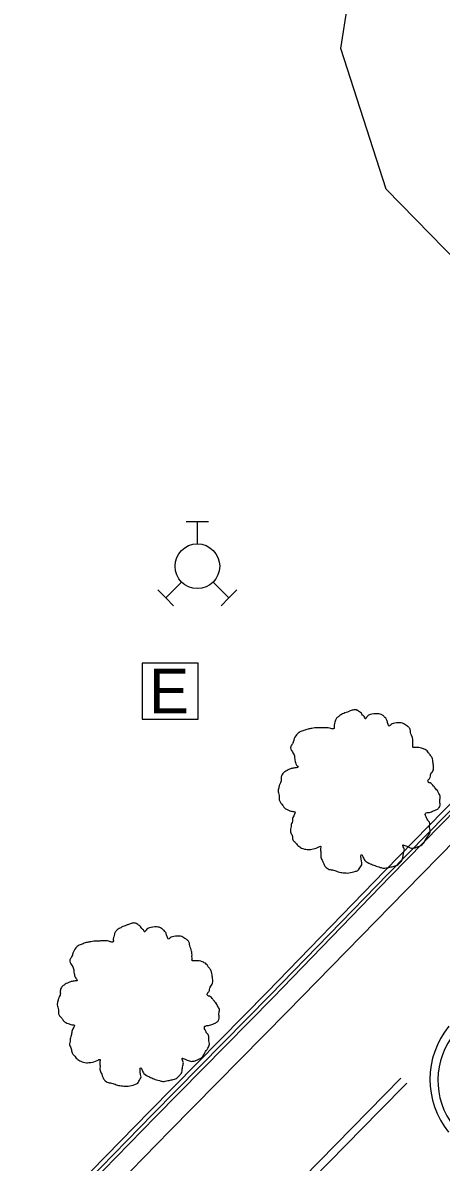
# Model space of a CAD drawing. Extents: x 2004847 to 2009016, y 1134161 to 1140101.
# Drawn here: x 2008292.1 to 2008329.5, y 1139615.9 to 1139717.9 of the extents above; entities that cross this region are included whole.
import ezdxf

# ---------------------------------------------------------------- set-up
doc = ezdxf.new("R2010")
doc.units = 0
for name, color, linetype in [('RD_EX_Curb', 7, 'Continuous'), ('RD_EX_Pavement_Markings', 7, 'Continuous'), ('RD_EX_Road', 7, 'Continuous'), ('RD_EX_SU_Elec', 7, 'Continuous'), ('RD_EX_UT', 7, 'Continuous'), ('RD_EX_VEG', 7, 'Continuous')]:
    doc.layers.add(name, color=color, linetype=linetype)

msp = doc.modelspace()

# ---------------------------------------------------------------- linework, layer by layer
at = {"layer": 'RD_EX_Curb'}
for points in [[(2008313.95, 1139631.15), (2008324.47, 1139642), (2008334.92, 1139652.7), (2008345.38, 1139663.43), (2008355.73, 1139674.16), (2008362.76, 1139681.32), (2008369.08, 1139687.77), (2008373.9, 1139692.85), (2008375.94, 1139695.31)], [(2008314.23, 1139630.88), (2008324.76, 1139641.72), (2008335.24, 1139652.39), (2008345.69, 1139663.14), (2008356.1, 1139673.82), (2008363.13, 1139680.99), (2008369.36, 1139687.52), (2008374.19, 1139692.61), (2008376.26, 1139695.09)], [(2008314.47, 1139630.64), (2008324.97, 1139641.51), (2008335.45, 1139652.2), (2008345.91, 1139662.92), (2008356.3, 1139673.64), (2008363.33, 1139680.8), (2008369.58, 1139687.31), (2008374.38, 1139692.45), (2008376.45, 1139694.96)], [(2008147.05, 1139457.63), (2008157.17, 1139468.78), (2008167.34, 1139479.93), (2008177.6, 1139490.95), (2008187.99, 1139502), (2008198.38, 1139512.83), (2008208.83, 1139523.6), (2008219.3, 1139534.36), (2008229.8, 1139545.07), (2008234.36, 1139549.78), (2008240.49, 1139556.23), (2008251, 1139566.93), (2008261.51, 1139577.61), (2008272.02, 1139588.33), (2008282.51, 1139599.04), (2008292.98, 1139609.77), (2008303.46, 1139620.49), (2008313.95, 1139631.15)], [(2008147.33, 1139457.38), (2008157.45, 1139468.53), (2008167.61, 1139479.68), (2008177.88, 1139490.7), (2008188.26, 1139501.74), (2008198.64, 1139512.57), (2008209.09, 1139523.35), (2008219.56, 1139534.1), (2008230.06, 1139544.81), (2008234.71, 1139549.44), (2008240.85, 1139555.89), (2008251.29, 1139566.64), (2008261.8, 1139577.33), (2008272.3, 1139588.06), (2008282.78, 1139598.77), (2008293.28, 1139609.48), (2008303.73, 1139620.23), (2008314.23, 1139630.88)], [(2008241.04, 1139555.7), (2008242.78, 1139557.49), (2008251.51, 1139566.43), (2008262.02, 1139577.12), (2008272.55, 1139587.82), (2008283.03, 1139598.53), (2008293.51, 1139609.26), (2008303.97, 1139619.99), (2008314.47, 1139630.64)]]:
    msp.add_lwpolyline(points, dxfattribs=at)
msp.add_ellipse((2008335.93, 1139623.25), major_axis=(-6.6, 1.24), ratio=0.998768, start_param=5.777021, end_param=7.134281, dxfattribs=at)
at = {"layer": 'RD_EX_Pavement_Markings'}
for points in [[(2008152.69, 1139442.67), (2008162.74, 1139453.81), (2008172.84, 1139464.89), (2008183.02, 1139475.91), (2008193.26, 1139486.87), (2008203.64, 1139497.7), (2008214.02, 1139508.52), (2008224.43, 1139519.32), (2008234.87, 1139530.1), (2008245.31, 1139540.87), (2008255.77, 1139551.62), (2008266.23, 1139562.38), (2008276.69, 1139573.13), (2008287.17, 1139583.86), (2008297.65, 1139594.59), (2008308.14, 1139605.31), (2008318.64, 1139616.02), (2008325.91, 1139623.46)], [(2008167.91, 1139458.51), (2008178.08, 1139469.54), (2008188.3, 1139480.51), (2008198.57, 1139491.45), (2008208.96, 1139502.27), (2008219.36, 1139513.07), (2008229.8, 1139523.85), (2008240.23, 1139534.63), (2008250.67, 1139545.4), (2008261.12, 1139556.16), (2008271.57, 1139566.92), (2008282.04, 1139577.67), (2008292.52, 1139588.39), (2008303.02, 1139599.11), (2008313.51, 1139609.83), (2008324.01, 1139620.54), (2008326.45, 1139622.99)]]:
    msp.add_lwpolyline(points, dxfattribs=at)
at = {"layer": 'RD_EX_Road'}
for points in [[(2008315.76, 1139629.38), (2008326.32, 1139640.22), (2008336.8, 1139650.91), (2008347.26, 1139661.64), (2008357.73, 1139672.33), (2008364.76, 1139679.49), (2008371.01, 1139685.99), (2008375.6, 1139691.43), (2008377.61, 1139694.15)], [(2008148.91, 1139455.96), (2008159.02, 1139467.1), (2008169.17, 1139478.24), (2008179.43, 1139489.25), (2008189.8, 1139500.27), (2008200.18, 1139511.09), (2008210.63, 1139521.87), (2008221.09, 1139532.62), (2008231.59, 1139543.33), (2008236.16, 1139548.03), (2008242.35, 1139554.43), (2008252.8, 1139565.18), (2008263.33, 1139575.84), (2008273.86, 1139586.54), (2008284.34, 1139597.25), (2008294.81, 1139607.99), (2008305.26, 1139618.73), (2008315.76, 1139629.38)]]:
    msp.add_lwpolyline(points, dxfattribs=at)
msp.add_ellipse((2008336.05, 1139623.33), major_axis=(-6.37, 4.04), ratio=0.999067, start_param=6.165399, end_param=7.525423, dxfattribs=at)
at = {"layer": 'RD_EX_SU_Elec'}
msp.add_lwpolyline([(2008307.78, 1139660.58), (2008302.78, 1139660.58), (2008302.78, 1139655.58), (2008307.78, 1139655.58)], close=True, dxfattribs=at)
at = {"layer": 'RD_EX_UT'}
for p, q in [((2008306.72, 1139673.25), (2008307.72, 1139673.25)), ((2008307.72, 1139671.25), (2008307.72, 1139673.25)), ((2008307.72, 1139673.25), (2008308.72, 1139673.25)), ((2008304.18, 1139667.13), (2008304.89, 1139666.42)), ((2008304.89, 1139666.42), (2008306.3, 1139667.83)), ((2008309.13, 1139667.83), (2008310.54, 1139666.42)), ((2008310.54, 1139666.42), (2008311.25, 1139667.13)), ((2008304.89, 1139666.42), (2008305.6, 1139665.71)), ((2008309.84, 1139665.71), (2008310.54, 1139666.42))]:
    msp.add_line(p, q, dxfattribs=at)
msp.add_circle((2008307.72, 1139669.25), 2, dxfattribs=at)
at = {"layer": 'RD_EX_VEG'}
msp.add_lwpolyline([(2008332.09, 1139788.37), (2008330.9, 1139795.8), (2008333.6, 1139805.97), (2008342.14, 1139812.2), (2008357.82, 1139800.97), (2008363, 1139794.75), (2008362.92, 1139789.94), (2008365.17, 1139755.73), (2008362.08, 1139745.13), (2008352.57, 1139734.46), (2008352.52, 1139720.58), (2008349.93, 1139715.56), (2008341.8, 1139698.24), (2008332.44, 1139694.95), (2008324.59, 1139702.97), (2008320.54, 1139715.57), (2008323.67, 1139735.59), (2008329.41, 1139744.01), (2008331.16, 1139775.58), (2008332.09, 1139788.37)], dxfattribs=at)
for points in [[(2008322.01, 1139656.38), (2008321.71, 1139656.4), (2008321.38, 1139656.3), (2008321.13, 1139656.2), (2008320.91, 1139656.13), (2008320.69, 1139656.03), (2008320.39, 1139655.85), (2008320.16, 1139655.65), (2008320.04, 1139655.4), (2008319.99, 1139655.18), (2008319.94, 1139654.9), (2008319.94, 1139654.73), (2008319.81, 1139654.7), (2008319.66, 1139654.73), (2008319.41, 1139654.8), (2008319.16, 1139654.8), (2008318.91, 1139654.8), (2008318.56, 1139654.78), (2008318.21, 1139654.78), (2008317.94, 1139654.73), (2008317.61, 1139654.68), (2008317.24, 1139654.55), (2008316.89, 1139654.43), (2008316.59, 1139654.18), (2008316.34, 1139653.7), (2008316.21, 1139653.35), (2008316.06, 1139653.1), (2008316.21, 1139652.65), (2008316.39, 1139652.3), (2008316.41, 1139652.1), (2008316.49, 1139651.68), (2008316.59, 1139651.46), (2008316.71, 1139651.26), (2008316.64, 1139651.23), (2008316.26, 1139651.18), (2008315.96, 1139651.08), (2008315.54, 1139650.86), (2008315.31, 1139650.63), (2008315.21, 1139650.31), (2008315.19, 1139649.96), (2008315.09, 1139649.76), (2008315.01, 1139649.48), (2008314.99, 1139649.41), (2008314.94, 1139649.08), (2008315.04, 1139648.63), (2008315.06, 1139648.28), (2008315.19, 1139648.06), (2008315.34, 1139647.88), (2008315.51, 1139647.63), (2008315.91, 1139647.41), (2008316.24, 1139647.31), (2008316.44, 1139647.28), (2008316.26, 1139646.78), (2008316.21, 1139646.43), (2008316.09, 1139646.03), (2008316.09, 1139645.96), (2008316.04, 1139645.48), (2008316.19, 1139645.16), (2008316.26, 1139644.78), (2008316.44, 1139644.56), (2008316.71, 1139644.26), (2008317.04, 1139644.03), (2008317.54, 1139643.91), (2008317.94, 1139643.93), (2008318.51, 1139644.11), (2008318.76, 1139644.18), (2008318.74, 1139644.01), (2008318.76, 1139643.63), (2008318.76, 1139643.21), (2008318.91, 1139642.88), (2008319.01, 1139642.61), (2008319.16, 1139642.36), (2008319.49, 1139642.13), (2008319.89, 1139642.06), (2008320.31, 1139641.91), (2008320.76, 1139641.83), (2008321.26, 1139641.81), (2008321.86, 1139641.96), (2008322.13, 1139642.08), (2008322.23, 1139642.26), (2008322.43, 1139642.63), (2008322.38, 1139642.86), (2008322.41, 1139643.46), (2008322.51, 1139643.28), (2008322.68, 1139642.93), (2008323.18, 1139642.63), (2008323.58, 1139642.46), (2008324.06, 1139642.31), (2008324.36, 1139642.23), (2008324.83, 1139642.31), (2008325.21, 1139642.38), (2008325.58, 1139642.51), (2008325.88, 1139642.78), (2008326.06, 1139643.06), (2008326.11, 1139643.33), (2008326.18, 1139643.71), (2008326.23, 1139643.88)], [(2008326.23, 1139643.88), (2008326.16, 1139644.06), (2008326.11, 1139644.31), (2008326.18, 1139644.28), (2008326.36, 1139644.23), (2008326.63, 1139644.11), (2008326.86, 1139644.03), (2008327.18, 1139644.06), (2008327.46, 1139644.16), (2008327.91, 1139644.43), (2008328.18, 1139644.91), (2008328.46, 1139645.31), (2008328.53, 1139645.63), (2008328.48, 1139645.86), (2008328.46, 1139646.36), (2008328.26, 1139646.61), (2008328.21, 1139646.73), (2008328.11, 1139647.13), (2008328.18, 1139647.18), (2008328.46, 1139647.23), (2008328.83, 1139647.36), (2008329.11, 1139647.48), (2008329.33, 1139647.66), (2008329.41, 1139647.88), (2008329.38, 1139648.28), (2008329.43, 1139648.68), (2008329.36, 1139648.83), (2008329.26, 1139648.98), (2008329.18, 1139649.18), (2008329.03, 1139649.33), (2008328.93, 1139649.48), (2008328.83, 1139649.58), (2008328.71, 1139649.73), (2008328.53, 1139649.86), (2008328.38, 1139649.91), (2008328.33, 1139650.06), (2008328.48, 1139650.26), (2008328.53, 1139650.36), (2008328.56, 1139650.58), (2008328.78, 1139650.93), (2008328.83, 1139651.33), (2008328.78, 1139651.76), (2008328.73, 1139652.03), (2008328.58, 1139652.3), (2008328.38, 1139652.55), (2008328.26, 1139652.73), (2008328.08, 1139652.85), (2008327.76, 1139652.98), (2008327.51, 1139653.03), (2008327.16, 1139653.03), (2008326.96, 1139653.08), (2008326.98, 1139653.13), (2008326.98, 1139653.28), (2008326.98, 1139653.55), (2008326.91, 1139654), (2008326.76, 1139654.5), (2008326.76, 1139654.53), (2008326.66, 1139654.78), (2008326.43, 1139654.98), (2008326.26, 1139655.08), (2008326.06, 1139655.2), (2008325.81, 1139655.23), (2008325.51, 1139655.23), (2008325.23, 1139655.18), (2008325.03, 1139655.08), (2008324.86, 1139654.95), (2008324.78, 1139655.1), (2008324.68, 1139655.4), (2008324.63, 1139655.55), (2008324.48, 1139655.73), (2008324.26, 1139655.93), (2008323.81, 1139656.05), (2008323.18, 1139655.98), (2008322.88, 1139655.78), (2008322.73, 1139655.6), (2008322.68, 1139655.73), (2008322.48, 1139655.93), (2008322.38, 1139656.1), (2008322.21, 1139656.23), (2008322.06, 1139656.33), (2008321.96, 1139656.38)], [(2008302.27, 1139637.3), (2008301.97, 1139637.33), (2008301.64, 1139637.23), (2008301.39, 1139637.13), (2008301.17, 1139637.05), (2008300.94, 1139636.95), (2008300.65, 1139636.78), (2008300.42, 1139636.58), (2008300.3, 1139636.33), (2008300.25, 1139636.1), (2008300.2, 1139635.83), (2008300.2, 1139635.65), (2008300.07, 1139635.63), (2008299.92, 1139635.65), (2008299.67, 1139635.73), (2008299.42, 1139635.73), (2008299.17, 1139635.73), (2008298.82, 1139635.7), (2008298.47, 1139635.7), (2008298.2, 1139635.65), (2008297.87, 1139635.6), (2008297.5, 1139635.48), (2008297.15, 1139635.35), (2008296.85, 1139635.1), (2008296.6, 1139634.63), (2008296.47, 1139634.28), (2008296.32, 1139634.03), (2008296.47, 1139633.58), (2008296.65, 1139633.23), (2008296.67, 1139633.03), (2008296.75, 1139632.61), (2008296.85, 1139632.38), (2008296.97, 1139632.18), (2008296.9, 1139632.16), (2008296.52, 1139632.11), (2008296.22, 1139632.01), (2008295.8, 1139631.78), (2008295.57, 1139631.56), (2008295.47, 1139631.23), (2008295.45, 1139630.88), (2008295.35, 1139630.68), (2008295.27, 1139630.41), (2008295.25, 1139630.33), (2008295.2, 1139630.01), (2008295.3, 1139629.56), (2008295.32, 1139629.21), (2008295.45, 1139628.98), (2008295.6, 1139628.81), (2008295.77, 1139628.56), (2008296.17, 1139628.33), (2008296.5, 1139628.23), (2008296.7, 1139628.21), (2008296.52, 1139627.71), (2008296.47, 1139627.36), (2008296.35, 1139626.96), (2008296.35, 1139626.88), (2008296.3, 1139626.41), (2008296.45, 1139626.08), (2008296.52, 1139625.71), (2008296.7, 1139625.48), (2008296.97, 1139625.18), (2008297.3, 1139624.96), (2008297.8, 1139624.83), (2008298.2, 1139624.86), (2008298.77, 1139625.03), (2008299.02, 1139625.11), (2008299, 1139624.93), (2008299.02, 1139624.56), (2008299.02, 1139624.13), (2008299.17, 1139623.81), (2008299.27, 1139623.53), (2008299.42, 1139623.28), (2008299.75, 1139623.06), (2008300.15, 1139622.98), (2008300.57, 1139622.83), (2008301.02, 1139622.76), (2008301.52, 1139622.73), (2008302.12, 1139622.88), (2008302.39, 1139623.01), (2008302.49, 1139623.18), (2008302.69, 1139623.56), (2008302.64, 1139623.78), (2008302.67, 1139624.38), (2008302.77, 1139624.21), (2008302.94, 1139623.86), (2008303.44, 1139623.56), (2008303.84, 1139623.38), (2008304.32, 1139623.23), (2008304.62, 1139623.16), (2008305.09, 1139623.23), (2008305.47, 1139623.31), (2008305.84, 1139623.43), (2008306.14, 1139623.71), (2008306.32, 1139623.98), (2008306.37, 1139624.26), (2008306.44, 1139624.63), (2008306.49, 1139624.81)], [(2008306.49, 1139624.81), (2008306.42, 1139624.98), (2008306.37, 1139625.23), (2008306.44, 1139625.21), (2008306.62, 1139625.16), (2008306.89, 1139625.03), (2008307.12, 1139624.96), (2008307.44, 1139624.98), (2008307.72, 1139625.08), (2008308.17, 1139625.36), (2008308.44, 1139625.83), (2008308.72, 1139626.23), (2008308.79, 1139626.56), (2008308.74, 1139626.78), (2008308.72, 1139627.28), (2008308.52, 1139627.53), (2008308.47, 1139627.66), (2008308.37, 1139628.06), (2008308.44, 1139628.11), (2008308.72, 1139628.16), (2008309.09, 1139628.28), (2008309.37, 1139628.41), (2008309.59, 1139628.58), (2008309.67, 1139628.81), (2008309.64, 1139629.21), (2008309.69, 1139629.61), (2008309.62, 1139629.76), (2008309.52, 1139629.91), (2008309.44, 1139630.11), (2008309.29, 1139630.26), (2008309.19, 1139630.41), (2008309.09, 1139630.51), (2008308.97, 1139630.66), (2008308.79, 1139630.78), (2008308.64, 1139630.83), (2008308.59, 1139630.98), (2008308.74, 1139631.18), (2008308.79, 1139631.28), (2008308.82, 1139631.51), (2008309.04, 1139631.86), (2008309.09, 1139632.26), (2008309.04, 1139632.68), (2008308.99, 1139632.96), (2008308.84, 1139633.23), (2008308.64, 1139633.48), (2008308.52, 1139633.66), (2008308.34, 1139633.78), (2008308.02, 1139633.91), (2008307.77, 1139633.95), (2008307.42, 1139633.95), (2008307.22, 1139634), (2008307.24, 1139634.05), (2008307.24, 1139634.2), (2008307.24, 1139634.48), (2008307.17, 1139634.93), (2008307.02, 1139635.43), (2008307.02, 1139635.45), (2008306.92, 1139635.7), (2008306.69, 1139635.9), (2008306.52, 1139636), (2008306.32, 1139636.13), (2008306.07, 1139636.15), (2008305.77, 1139636.15), (2008305.49, 1139636.1), (2008305.29, 1139636), (2008305.12, 1139635.88), (2008305.04, 1139636.03), (2008304.94, 1139636.33), (2008304.89, 1139636.48), (2008304.74, 1139636.65), (2008304.52, 1139636.85), (2008304.07, 1139636.98), (2008303.44, 1139636.9), (2008303.14, 1139636.7), (2008302.99, 1139636.53), (2008302.94, 1139636.65), (2008302.74, 1139636.85), (2008302.64, 1139637.03), (2008302.47, 1139637.15), (2008302.32, 1139637.25), (2008302.22, 1139637.3)]]:
    msp.add_spline(points, degree=3, dxfattribs=at)

# ---------------------------------------------------------------- texts
at = {"layer": 'RD_EX_SU_Elec'}
msp.add_text('E', height=4, dxfattribs=at).set_placement((2008303.4, 1139656.08))

doc.saveas('drawing.dxf')
